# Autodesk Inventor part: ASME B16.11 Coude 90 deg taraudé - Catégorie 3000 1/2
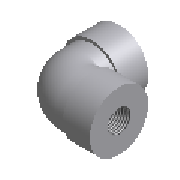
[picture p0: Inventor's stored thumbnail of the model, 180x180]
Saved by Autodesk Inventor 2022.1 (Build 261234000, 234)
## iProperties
Created: 2021-02
Part Number: ASME B16.11 Coude 90 deg taraudé - Catégorie 3000 1/2
Material: Acier
Description: Coude 90° taraudé - Forgé - Catégorie 3000
Document SubType Name: Modeling
Standard: ASME B16.11
Designer: Fabian
Standard Revision: 2011
Standards Organization: ANSI
Language: fr-FR
Size Designation: 1/2
Categories: <MemberInstance><Categories><Category DisplayName="Tubes et tuyaux" InternalName="4347fa0f-2144-441d-94cd-e3e15c92b736" Mnemonic="TUBEANDPIPE"><CategoryParamete
Density: 1 g/cm^3
Appearance: Plaque
IsCustomPart: 0
NAME: PIPING: ASME B16.11 90 Deg Elbow Threaded - Class 3000
DATA: <meta><inlinegroups number="0" deflen="0"></inlinegroups><connections number="2"></connections><angles><a>1.57079632679489</a></angles></meta>
Author: Fabian
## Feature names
1. Sweep1
2. Revolve1
3. Revolve2
4. Revolve3
5. Revolve4
6. Sweep2
## Parameters: MD = 18.32077 mm, A = 33.274 mm, L2 = 13.55598 mm, G = 4.0894 mm, d0 = 18.32077 mm, d1 = 38.1 mm, d2 = 0.3124 mm, d3 = 0.3124 mm, d4 = 18.32077 mm, d5 = 38.1 mm, H = 38.1 mm, d6 = 13.55598 mm, d7 = 26.1112 mm, d8 = 13.55598 mm, d9 = 26.1112 mm, d10 = 0, d11 = 9.9822 mm, d12 = 9.9822 mm, d13 = 17.145 mm, d14 = 0, d101 = 90 deg, d102 = 90 deg, d105 = 25.4 mm, d106 = 0, d107 = 25.4 mm, d108 = 0, d15 = 33.274 mm, d16 = 16.637 mm, d17 = 33.274 mm, d18 = 16.637 mm, d19 = 34.29 mm, d20 = 34.29 mm, d21 = 9.9822 mm, d116 = 90 deg, d117 = 90 deg, d22 = 13.05564 mm, d23 = 0, d122 = 0, d123 = 0, Size_Designation = 5 mm
